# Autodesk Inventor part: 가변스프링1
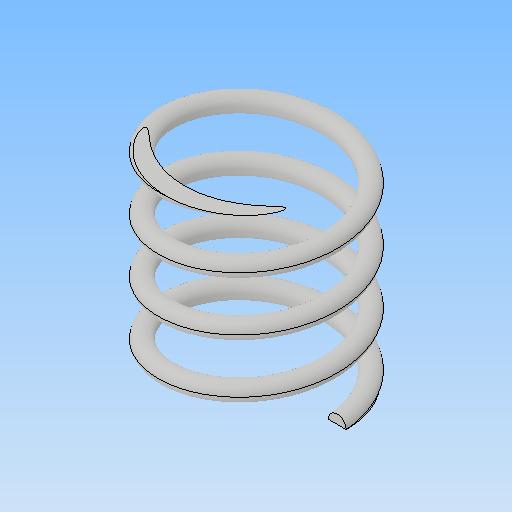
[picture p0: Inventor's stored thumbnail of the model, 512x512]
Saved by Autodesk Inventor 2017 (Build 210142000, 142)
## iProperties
Part Number: 가변스프링1
Material: 일반
Document SubType Name: Modeling
Designer: MRC
Density: 1 g/cm^3
Appearance: 기본값
Author: MRC
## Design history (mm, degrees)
sketch "스케치1"
  geometry: L1 (0, 0)-(0, 22.5); L2 (0, 22.5)-(9, 22.5); L3 (0, 0)-(9, 0); C1 r 1 at (9, 0)
  constraints: 6 end point, 1 centre point, 1 coincident, 1 parallel, 1 perpendicular, 1 vertical
  dimensions: "d0" = 22.5 distance of L1.start L1.end (derived); "d1" = 9 distance of L1.end L2.end; "d2" = 9 distance of L1.start L3.end; "d3" = 2 diameter of C1
feature "코일1" sketch "스케치1" pitch "d4" = 10; turns "d6" = 5; dims "d5" = 30, "d7" = 0, angle "d8" = 90 deg, angle "d9" = 90 deg, "d10" = 0, "d11" = 0
sketch "스케치2"
  geometry: L1 (22.5, 15.094)-(0, 15.094); L2 (0, 15.094)-(0, -15.094); L3 (0, -15.094)-(22.5, -15.094); L4 (22.5, -15.094)-(22.5, 15.094); 3 further points
  constraints: 8 end point, 2 midpoint, 2 parallel, 1 coincident, 1 horizontal, 1 horizontal alignment, 1 perpendicular
  dimensions: "d12" = 22.5 distance of L2.end L3.end (= d0); "d13" = 30.18785 distance of L3.end L1.start
extrude "돌출1" sketch "스케치2" stored distance "d14" = 0; taper "d15" = 0 deg
node "솔리드1"
